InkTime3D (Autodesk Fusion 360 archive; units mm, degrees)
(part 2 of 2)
sketch "Sketch24" plane through (0, 0, 12) normal (0, 0, -1) x axis (1, 0, 0)
  line L1 (-10, 22.5) -> (9.4445, 22.5)
  line L2 (-17, -15.5) -> (-17, 15.5)
  line L3 (9.3, -22.5) -> (-10, -22.5)
  line L4 (17, 15.5) -> (17, -15.5)
  line L5 (-13.9332, 13.1436) -> (-13.9332, -15.025)
  line L6 (13.6766, -15.025) -> (13.6766, 13.1436)
  line L7 (-14.0414, 19.2904) -> (-16.0414, 19.2904)
  line L8 (-14.0414, 20.2904) -> (-14.0414, 19.2904)
  line L9 (-16.0414, 20.2904) -> (-14.0414, 20.2904)
  line L10 (-16.0414, 19.2904) -> (-16.0414, 20.2904)
  line L11 (14.5006, 19.2904) -> (16.5006, 19.2904)
  line L12 (14.5006, 20.2904) -> (14.5006, 19.2904)
  line L13 (16.5006, 20.2904) -> (14.5006, 20.2904)
  line L14 (16.5006, 19.2904) -> (16.5006, 20.2904)
  line L15 (11, 23.5) -> (-11, 23.5)
  line L16 (15.1041, 20.2904) -> (16.885, 20.2904)
  line L17 (-16.885, 20.2904) -> (-15.1041, 20.2904)
  line L18 (12, -24.5) -> (-12, -24.5)
  line L19 (19, 17.5) -> (19, -17.5)
  line L20 (-12, 24.5) -> (12, 24.5)
  line L21 (-19, -17.5) -> (-19, 17.5)
  line L22 (6.5, -21) -> (6.5, -17.5)
  line L23 (-6.5, -21) -> (6.5, -21)
  line L24 (-6.5, -17.5) -> (-6.5, -21)
  line L25 (6.5, -17.5) -> (-6.5, -17.5)
  line L26 (-8.9719, -20.65) -> (-8.9719, -17.1553)
  line L27 (-11.9719, -20.65) -> (-8.9719, -20.65)
  line L28 (-11.9719, -17.1553) -> (-11.9719, -20.65)
  line L29 (-8.9719, -17.1553) -> (-11.9719, -17.1553)
  line L30 (-16.0414, 19.0358) -> (-16.0414, 19.2904)
  line L31 (12.034, -22.2) -> (12.0273, -22.2)
  line L32 (17.4198, 19.2904) -> (15.885, 19.2904)
  line L33 (18, 8.6) -> (18, 16.5)
  line L34 (18, 2.4) -> (18, 8.6)
  line L35 (18, -2.4) -> (18, 2.4)
  line L36 (18, -8.6) -> (18, -2.4)
  line L37 (18, -16.5) -> (18, -8.6)
  line L38 (-11, -23.5) -> (11, -23.5)
  line L39 (-18, -10.5) -> (-18, -16.5)
  line L40 (-18, -4.5) -> (-18, -10.5)
  line L41 (-18, 4.5) -> (-18, -4.5)
  line L42 (-18, 10.5) -> (-18, 4.5)
  line L43 (-18, 16.5) -> (-18, 10.5)
  line L44 (-16.0414, 19.2904) -> (-17.4198, 19.2904)
  line L45 (13.6766, 13.1436) -> (-13.9332, 13.1436)
  line L46 (-13.9332, -15.025) -> (13.6766, -15.025)
  arc A1 centre (10, 15.5) radius 7 clockwise from (13.5033, 21.5603) to (15.1041, 20.2904)
  arc A2 centre (-10, 15.5) radius 7 clockwise from (-15.1041, 20.2904) to (-10, 22.5)
  arc A3 centre (-10, -15.5) radius 7 clockwise from (-10, -22.5) to (-17, -15.5)
  arc A4 centre (10, -15.5) radius 7 clockwise from (12.0273, -22.2) to (10.5255, -22.4802)
  arc A5 centre (-11, 16.5) radius 7 clockwise from (-16.885, 20.2904) to (-11, 23.5)
  arc A6 centre (11, 16.5) radius 7 clockwise from (11, 23.5) to (12.5807, 23.3192)
  arc A7 centre (12.9379, 22.3852) radius 1 clockwise from (12.5807, 23.3192) to (13.7802, 22.9242)
  arc A8 centre (11, 16.5) radius 7 clockwise from (13.7802, 22.9242) to (16.885, 20.2904)
  arc A9 centre (12.9379, 22.3852) radius 1 clockwise from (13.5033, 21.5603) to (11.9512, 22.2226)
  arc A10 centre (10, 15.5) radius 7 clockwise from (11.4373, 22.3508) to (11.9512, 22.2226)
  arc A11 centre (10.4379, 22.3852) radius 1 clockwise from (11.4373, 22.3508) to (9.4445, 22.5)
  arc A12 centre (-12, -17.5) radius 7 clockwise from (-12, -24.5) to (-19, -17.5)
  arc A13 centre (12, -17.5) radius 7 clockwise from (19, -17.5) to (12, -24.5)
  arc A14 centre (12, 17.5) radius 7 clockwise from (12, 24.5) to (19, 17.5)
  arc A15 centre (-12, 17.5) radius 7 clockwise from (-19, 17.5) to (-12, 24.5)
  arc A16 centre (-10, 15.5) radius 7 clockwise from (-17, 15.5) to (-16.0414, 19.0358)
  arc A17 centre (9.9, -21.7) radius 1 clockwise from (9.3, -22.5) to (10.5255, -22.4802)
  arc A18 centre (12.9, -21.7) radius 1 clockwise from (12.034, -22.2) to (13.8382, -21.3539)
  arc A19 centre (10, -15.5) radius 7 clockwise from (15.3386, -20.0276) to (13.8382, -21.3539)
  arc A20 centre (15.9, -19.2) radius 1 clockwise from (15.3386, -20.0276) to (16.4005, -18.3343)
  arc A21 centre (10, -15.5) radius 7 clockwise from (17, -15.5) to (16.4005, -18.3343)
  arc A22 centre (10, 15.5) radius 7 clockwise from (15.885, 19.2904) to (17, 15.5)
  arc A23 centre (11, 16.5) radius 7 clockwise from (17.4198, 19.2904) to (18, 16.5)
  arc A24 centre (11, -16.5) radius 7 clockwise from (18, -16.5) to (11, -23.5)
  arc A25 centre (-11, -16.5) radius 7 clockwise from (-11, -23.5) to (-18, -16.5)
  arc A26 centre (-11, 16.5) radius 7 clockwise from (-18, 16.5) to (-17.4198, 19.2904)
  circle C1 centre (12.9379, 19.8852) radius 1
  circle C2 centre (12.9, -19.2) radius 1
  circle C3 centre (10.4379, 19.8852) radius 1
  circle C4 centre (9.9, -19.2) radius 1
  point P23 (-16.0414, 19.2904)
  point P24 (-14.0414, 19.2904)
  point P26 (-16.0414, 20.2904)
  point P27 (16.5006, 19.2904)
  point P28 (14.5006, 19.2904)
  point P30 (16.5006, 20.2904)
  horizontal L7
  vertical L8
  horizontal L9
  vertical L10
  horizontal L11
  vertical L12
  horizontal L13
  vertical L14
  dimension "d238" distance P23 P24 = 2
  dimension "d239" distance P23 P26 = 1
  dimension "d242" distance P27 P28 = 2
  dimension "d243" distance P27 P30 = 1
extrude "Extrude84" add sketch "Sketch24" profile of L7 L8 L9 L10 along normal blind 2
extrude "Extrude85" add sketch "Sketch24" profile of L11 L12 L13 L14 along normal blind 2
fillet "Fillet13" radius 1
delete_face "DeleteFace3"
delete_face "DeleteFace4"
extrude "Extrude86" cut of existing geometry blind 17.5
extrude "Extrude87" cut of existing geometry blind -0.14 bodies "BottomCase (1)"
extrude "Extrude88" cut of existing geometry blind -1
move "Move14"
extrude "Extrude89" add of existing geometry blind 0.6 bodies "BottomCase (1)"
move "Move15"
move "Move16"
extrude "Extrude90" cut of existing geometry blind -0.6
extrude "Extrude91" cut of existing geometry blind -0.6
extrude "Extrude92" add of existing geometry blind 0.5
extrude "Extrude93" add of existing geometry blind 1.5
extrude "Extrude94" cut of existing geometry blind -0.4
extrude "Extrude95" cut of existing geometry blind -0.4
extrude "Extrude96" cut of existing geometry blind -4
delete_face "DeleteFace5"
delete_face "DeleteFace6"
delete_face "DeleteFace7"
delete_face "DeleteFace8"
sketch "Sketch25" plane through (18, 0, 0) normal (-1, 0, 0) x axis (0, -1, 0)
  line L1 (16.5, 6.5) -> (-16.5, 6.5)
  line L2 (16.5, 12.6) -> (16.5, 6.5)
  line L3 (-16.5, 12.6) -> (16.5, 12.6)
  line L4 (-16.5, 6.5) -> (-16.5, 12.6)
  line L5 (-2.3855, 10.6) -> (-2.3855, 12.6)
  line L6 (-8.5855, 10.6) -> (-2.3855, 10.6)
  line L7 (-8.5855, 12.6) -> (-8.5855, 10.6)
  line L8 (2.4, 10.6) -> (2.4, 12.6)
  line L9 (8.6, 10.6) -> (2.4, 10.6)
  line L10 (8.6, 12.6) -> (8.6, 10.6)
  circle C1 centre (11, 8.8) radius 2.25
  circle C2 centre (0, 8.8) radius 2.25
  circle C3 centre (-11, 8.8) radius 2.25
  point P9 (-2.3855, 12.6)
  point P12 (-8.5855, 12.6)
  point P13 (2.4, 12.6)
  point P16 (8.6, 12.6)
  point P10 (-2.3855, 10.6)
  point P11 (-8.5855, 10.6)
  vertical L5
  coincident L3 P9
  horizontal L6
  coincident L3 P12
  perpendicular L3 L7
  coincident L3 P13
  perpendicular L3 L8
  perpendicular L8 L9
  coincident L3 P16
  perpendicular L3 L10
  dimension "d270" distance P9 P10 = 2
  dimension "d271" distance P10 P11 = 6.2
move "Move17"
extrude "Extrude97" cut sketch "Sketch25" profile of L3 L5 L6 L7 L8 L9 L10 against normal blind 2 taper -45
chamfer "Chamfer3" distance 0.2
fillet "Fillet14" radius 322.55
move "Move18"
sketch "Sketch26" plane through (-18, 0, 0) normal (1, 0, 0) x axis (0, 1, 0)
  line L1 (16.5, 6.5) -> (-16.5, 6.5)
  line L2 (16.5, 12.6) -> (16.5, 6.5)
  line L3 (-16.5, 12.6) -> (16.5, 12.6)
  line L4 (-16.5, 6.5) -> (-16.5, 12.6)
  line L5 (-3.19, 8.26) -> (3.19, 8.26)
  line L6 (-4.47, 10.18) -> (-4.47, 9.54)
  line L7 (3.19, 11.46) -> (-3.19, 11.46)
  line L8 (4.47, 9.54) -> (4.47, 10.18)
  line L9 (-10.5, 10.6) -> (-10.5, 12.6)
  line L10 (-4.5, 10.6) -> (-10.5, 10.6)
  line L11 (-4.5, 12.6) -> (-4.5, 10.6)
  line L12 (4.5, 10.6) -> (4.5, 12.6)
  line L13 (10.5, 10.6) -> (4.5, 10.6)
  line L14 (10.5, 12.6) -> (10.5, 10.6)
  arc A1 centre (-3.19, 9.54) radius 1.28 clockwise from (-3.19, 8.26) to (-4.47, 9.54)
  arc A2 centre (-3.19, 10.18) radius 1.28 clockwise from (-4.47, 10.18) to (-3.19, 11.46)
  arc A3 centre (3.19, 10.18) radius 1.28 clockwise from (3.19, 11.46) to (4.47, 10.18)
  arc A4 centre (3.19, 9.54) radius 1.28 clockwise from (4.47, 9.54) to (3.19, 8.26)
  point P18 (-10.5, 12.6)
  point P21 (-4.5, 12.6)
  point P22 (4.5, 12.6)
  point P25 (10.5, 12.6)
  point P19 (-10.5, 10.6)
  point P20 (-4.5, 10.6)
  point P23 (4.5, 10.6)
  point P24 (10.5, 10.6)
  coincident L3 P18
  perpendicular L3 L9
  perpendicular L9 L10
  coincident L3 P21
  perpendicular L3 L11
  coincident L3 P22
  perpendicular L3 L12
  perpendicular L12 L13
  coincident L3 P25
  perpendicular L3 L14
  dimension "d278" distance P19 P20 = 6
  dimension "d279" distance P23 P24 = 6
move "Move19"
extrude "Extrude98" cut sketch "Sketch26" profile of L3 L9 L10 L11 L12 L13 L14 against normal blind 2 taper -45
chamfer "Chamfer4" distance 0.2
fillet "Fillet15" radius 379.25
move "Move20"
extrude "Extrude99" cut of existing geometry blind -2
sketch "Sketch27" plane through (0, -24.5, 0) normal (0, -1, 0) x axis (1, 0, 0)
  line L1 (12, 1) -> (-12, 1)
  line L2 (12, 12.6) -> (12, 1)
  line L3 (-12, 12.6) -> (12, 12.6)
  line L4 (-12, 1) -> (-12, 12.6)
  line L5 (10, 1) -> (0, 1)
  line L6 (-10, 1) -> (0, 1)
  line L7 (-12, 1) -> (-10, 1)
  line L8 (-12, 9) -> (-12, 1)
  line L9 (-10, 9) -> (-12, 9)
  line L10 (-10, 1) -> (-10, 9)
  line L11 (12, 1) -> (10, 1)
  line L12 (12, 9) -> (12, 1)
  line L13 (10, 9) -> (12, 9)
  line L14 (10, 1) -> (10, 9)
  point P6 (0, 1)
  point P7 (10, 1)
  point P8 (-10, 1)
  point P9 (-12, 1)
  point P11 (-10, 9)
  point P14 (10, 9)
  midpoint L1 P6
  parallel L1 L5
  parallel L1 L6
  horizontal L7
  vertical L8
  horizontal L9
  vertical L10
  horizontal L11
  vertical L12
  horizontal L13
  vertical L14
  dimension "d288" distance P6 P7 = 10
  dimension "d289" distance P6 P8 = 10
  dimension "d290" distance P8 P9 = 2
  dimension "d291" distance P8 P11 = 8
  dimension "d292" distance P7 P14 = 8
extrude "Extrude100" new body sketch "Sketch27" profile of L1 L2 L4 L7 L8 L9 L10 L11 L12 L13 L14 along normal blind 3
mirror "Mirror1" mirrorStitchTolerance 0.1
combine "Combine2"
fillet "Fillet16" radius 3.5
fillet "Fillet17" radius 4
sketch "Sketch28" plane through (-10, 0, 0) normal (1, 0, 0) x axis (0, 1, 0)
  line L1 (-24.5, 12.4641) -> (-24.5, 1)
  line L2 (-27.5, 4.873) -> (-27.5, 6.7195)
  arc A1 centre (-23.5, 4.873) radius 4 clockwise from (-24.5, 1) to (-27.5, 4.873)
  arc A2 centre (-28, 12.4641) radius 3.5 clockwise from (-24.5, 12.4641) to (-26, 9.5918)
  arc A3 centre (-24, 6.7195) radius 3.5 clockwise from (-27.5, 6.7195) to (-26, 9.5918)
  circle C1 centre (-26, 5.1) radius 0.45
  dimension "d301" diameter C1 = 0.9
extrude "Extrude101" cut sketch "Sketch28" profile of C1 against normal blind 1 and along normal blind 21
mirror "Mirror2" mirrorStitchTolerance 0.1
sketch "Sketch29" plane through (0, 0, 12.6) normal (0, 0, -1) x axis (1, 0, 0)
  line L1 (-10, 22.5) -> (9.4445, 22.5)
  line L2 (-17, -15.5) -> (-17, 15.5)
  line L3 (9.3, -22.5) -> (-10, -22.5)
  line L4 (17, 15.5) -> (17, -15.5)
  line L5 (16, -8.5) -> (17, -8.5)
  line L6 (16, -2.5) -> (16, -8.5)
  line L7 (17, -2.5) -> (16, -2.5)
  line L8 (17, -8.5) -> (17, -2.5)
  line L9 (16, 2.5) -> (17, 2.5)
  line L10 (16, 8.5) -> (16, 2.5)
  line L11 (17, 8.5) -> (16, 8.5)
  line L12 (17, 2.5) -> (17, 8.5)
  line L13 (-16.2, -4.5) -> (-17, -4.5)
  line L14 (-16.2, -10.5) -> (-16.2, -4.5)
  line L15 (-17, -10.5) -> (-16.2, -10.5)
  line L16 (-17, -4.5) -> (-17, -10.5)
  line L17 (-16.2, 4.5) -> (-17, 4.5)
  line L18 (-16.2, 10.4971) -> (-16.2, 4.5)
  line L19 (-17, 10.4971) -> (-16.2, 10.4971)
  line L20 (-17, 4.5) -> (-17, 10.4971)
  line L21 (-11.9719, -20.65) -> (-6.9719, -20.65)
  line L22 (-11.9719, -17.1553) -> (-11.9719, -20.65)
  line L23 (-6.9719, -17.1553) -> (-11.9719, -17.1553)
  line L24 (-6.9719, -20.65) -> (-6.9719, -17.1553)
  line L25 (14.5006, 20.2904) -> (16.885, 20.2904)
  line L26 (14.5006, 20.7904) -> (14.5006, 20.2904)
  line L27 (14.5838, 20.7904) -> (14.5006, 20.7904)
  line L28 (-14.0414, 20.2904) -> (-14.0414, 21.2155)
  line L29 (-16.885, 20.2904) -> (-14.0414, 20.2904)
  line L30 (11, 23.5) -> (-11, 23.5)
  line L31 (17.4198, 19.2904) -> (15.885, 19.2904)
  line L32 (18, 8.6) -> (18, 16.5)
  line L33 (18, 2.4) -> (18, 8.6)
  line L34 (18, -2.4) -> (18, 2.4)
  line L35 (18, -8.6) -> (18, -2.4)
  line L36 (18, -16.5) -> (18, -8.6)
  line L37 (-11, -23.5) -> (11, -23.5)
  line L38 (-18, -10.5) -> (-18, -16.5)
  line L39 (-18, -4.5) -> (-18, -10.5)
  line L40 (-18, 4.5) -> (-18, -4.5)
  line L41 (-18, 10.5) -> (-18, 4.5)
  line L42 (-18, 16.5) -> (-18, 10.5)
  line L43 (-16.0414, 19.2904) -> (-17.4198, 19.2904)
  line L44 (-16.0414, 19.0358) -> (-16.0414, 19.2904)
  line L45 (12.034, -22.2) -> (12.0273, -22.2)
  line L46 (6.5, -21) -> (6.5, -17.5)
  line L47 (-6.5, -21) -> (6.5, -21)
  line L48 (-6.5, -17.5) -> (-6.5, -21)
  line L49 (6.5, -17.5) -> (-6.5, -17.5)
  line L50 (-13.9332, 13.1436) -> (-13.9332, -15.025)
  line L51 (13.6766, 13.1436) -> (-13.9332, 13.1436)
  line L52 (13.6766, -15.025) -> (13.6766, 13.1436)
  line L53 (-13.9332, -15.025) -> (13.6766, -15.025)
  line L54 (-12, 24.5) -> (12, 24.5)
  line L55 (-19, -17.5) -> (-19, 17.5)
  line L56 (12, -24.5) -> (-12, -24.5)
  line L57 (19, 17.5) -> (19, -17.5)
  arc A1 centre (10, 15.5) radius 7 clockwise from (13.5033, 21.5603) to (14.5838, 20.7904)
  arc A2 centre (-10, 15.5) radius 7 clockwise from (-14.0414, 21.2155) to (-10, 22.5)
  arc A3 centre (-10, -15.5) radius 7 clockwise from (-10, -22.5) to (-17, -15.5)
  arc A4 centre (10, -15.5) radius 7 clockwise from (12.0273, -22.2) to (10.5255, -22.4802)
  arc A5 centre (12.9379, 22.3852) radius 1 clockwise from (13.5033, 21.5603) to (11.9512, 22.2226)
  arc A6 centre (10, 15.5) radius 7 clockwise from (11.4373, 22.3508) to (11.9512, 22.2226)
  arc A7 centre (10.4379, 22.3852) radius 1 clockwise from (11.4373, 22.3508) to (9.4445, 22.5)
  arc A8 centre (-11, 16.5) radius 7 clockwise from (-16.885, 20.2904) to (-11, 23.5)
  arc A9 centre (11, 16.5) radius 7 clockwise from (11, 23.5) to (12.5807, 23.3192)
  arc A10 centre (12.9379, 22.3852) radius 1 clockwise from (12.5807, 23.3192) to (13.7802, 22.9242)
  arc A11 centre (11, 16.5) radius 7 clockwise from (13.7802, 22.9242) to (16.885, 20.2904)
  arc A12 centre (11, 16.5) radius 7 clockwise from (17.4198, 19.2904) to (18, 16.5)
  arc A13 centre (11, -16.5) radius 7 clockwise from (18, -16.5) to (11, -23.5)
  arc A14 centre (-11, -16.5) radius 7 clockwise from (-11, -23.5) to (-18, -16.5)
  arc A15 centre (-11, 16.5) radius 7 clockwise from (-18, 16.5) to (-17.4198, 19.2904)
  arc A16 centre (-10, 15.5) radius 7 clockwise from (-17, 15.5) to (-16.0414, 19.0358)
  arc A17 centre (9.9, -21.7) radius 1 clockwise from (9.3, -22.5) to (10.5255, -22.4802)
  arc A18 centre (12.9, -21.7) radius 1 clockwise from (12.034, -22.2) to (13.8382, -21.3539)
  arc A19 centre (10, -15.5) radius 7 clockwise from (15.3386, -20.0276) to (13.8382, -21.3539)
  arc A20 centre (15.9, -19.2) radius 1 clockwise from (15.3386, -20.0276) to (16.4005, -18.3343)
  arc A21 centre (10, -15.5) radius 7 clockwise from (17, -15.5) to (16.4005, -18.3343)
  arc A22 centre (10, 15.5) radius 7 clockwise from (15.885, 19.2904) to (17, 15.5)
  circle C1 centre (12.9379, 19.8852) radius 1
  circle C2 centre (12.9, -19.2) radius 1
  circle C3 centre (10.4379, 19.8852) radius 1
  circle C4 centre (9.9, -19.2) radius 1
  arc A23 centre (12, 17.5) radius 7 clockwise from (12, 24.5) to (19, 17.5)
  arc A24 centre (-12, 17.5) radius 7 clockwise from (-19, 17.5) to (-12, 24.5)
  arc A25 centre (-12, -17.5) radius 7 clockwise from (-12, -24.5) to (-19, -17.5)
  arc A26 centre (12, -17.5) radius 7 clockwise from (19, -17.5) to (12, -24.5)
  point P19 (17, -8.5)
  point P23 (17, 2.5)
  point P27 (-17, -4.5)
  point P31 (-17, 4.5)
  horizontal L5
  vertical L6
  horizontal L7
  vertical L8
  coincident L4 P19
  horizontal L9
  vertical L10
  horizontal L11
  vertical L12
  coincident L4 P23
  horizontal L13
  vertical L14
  horizontal L15
  vertical L16
  coincident L2 P27
  horizontal L17
  vertical L18
  horizontal L19
  vertical L20
  coincident L2 P31
extrude "Extrude102" add sketch "Sketch29" profile of L2 L4 L5 L6 L7 L8 L9 L10 L11 L12 L13 L14 L15 L16 L17 L18 L19 L20 along normal blind 2
extrude "Extrude103" cut of existing geometry blind -11
extrude "Extrude104" cut of existing geometry blind -7
extrude "Extrude105" add of existing geometry blind 2
extrude "Extrude106" add of existing geometry blind 5
offset_faces "OffsetFaces1" distance 1
offset_faces "OffsetFaces2" distance 1
offset_faces "OffsetFaces3" distance 2
offset_faces "OffsetFaces4" distance 1.5
offset_faces "OffsetFaces5" distance 1
offset_faces "OffsetFaces6" distance 1
offset_faces "OffsetFaces7" distance 1
offset_faces "OffsetFaces8" distance 1
offset_faces "OffsetFaces9" distance 1
extrude "Extrude53" add sketch "Sketch20" along normal blind 1
extrude "Extrude54" add of existing geometry blind 1.5
sketch "Sketch21" plane through (0, 17.6, 0) normal (0, -1, 0) x axis (1, 0, 0)
  line L1 (-3, 12) -> (3, 12)
  line L2 (-3, 9.5) -> (-3, 12)
  line L3 (3, 9.5) -> (-3, 9.5)
  line L4 (3, 12) -> (3, 9.5)
  line L5 (3, 9.5) -> (-3, 9.5)
  line L6 (3, 11) -> (3, 9.5)
  line L7 (-3, 11) -> (3, 11)
  line L8 (-3, 9.5) -> (-3, 11)
  point P8 (3, 11)
  point P4 (-3, 9.5)
  point P6 (-3, 9.5)
  horizontal L5
  vertical L6
  horizontal L7
  vertical L8
  coincident L4 P8
  coincident P4 P6
extrude "Extrude55" add sketch "Sketch21" profile of L2 L3 L4 L5 L6 L7 L8 along normal blind 1
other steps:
base_feature "Base Feature1" bodies "Button1", "Button2"
base_feature "Base Feature2" bodies "Button1 (1)", "Button3"
named bodies: "BottomCase", "Battery", "TopCase", "Button1", "Button2", "Button1 (1)", "Button3", "Pana", "BottomCase (1)", "TopCase (1)"

design "Baterie"
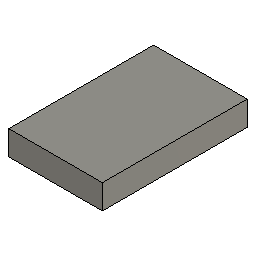
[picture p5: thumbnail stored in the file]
description: Part Number
part number: 2026-04-18-21-57-17-208
base_feature "Base Feature"

design "Shaker"
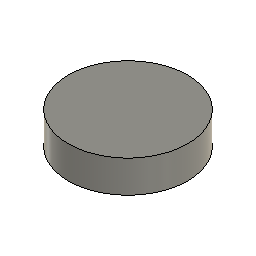
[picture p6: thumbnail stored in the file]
description: Part Number
part number: 2026-04-18-22-21-12-256
base_feature "Base Feature"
